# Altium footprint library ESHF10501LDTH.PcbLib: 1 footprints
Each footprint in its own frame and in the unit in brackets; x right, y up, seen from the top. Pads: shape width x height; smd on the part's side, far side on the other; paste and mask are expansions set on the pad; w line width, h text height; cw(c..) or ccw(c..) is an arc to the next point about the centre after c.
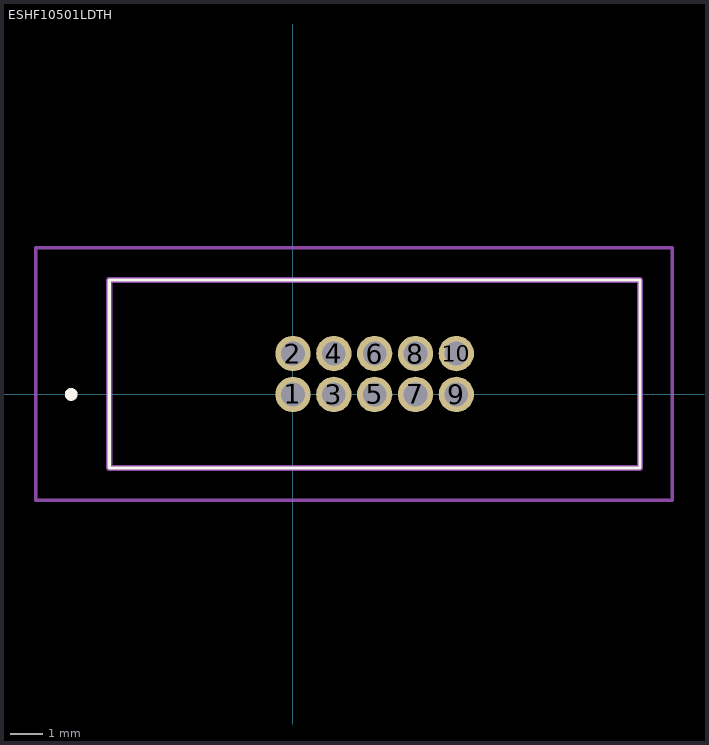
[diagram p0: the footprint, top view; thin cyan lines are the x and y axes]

## ESHF10501LDTH [mm]
pads (10):
  round 1.1 hole 0.74: 1(0,0) 2(0,1.27) 3(1.27,0) 4(1.27,1.27) 5(2.54,0) 6(2.54,1.27) 7(3.81,0) 8(3.81,1.27) 9(5.08,0) 10(5.08,1.27)
Top Overlay:
  lines w0.1: -5.715,-2.29 10.795,-2.29 10.795,3.56 -5.715,3.56 -5.715,-2.29
  lines w0.2: -7,0 -7,0 ; -7,0 ccw(c-6.9,0) -6.8,0 ; -7,0 cw(c-6.9,0) -6.8,0 ; -6.8,0 -6.8,0
Mechanical 15:
  lines w0.2: -5.715,-2.29 10.795,-2.29 10.795,3.56 -5.715,3.56 -5.715,-2.29
Mechanical 20:
  lines w0.1: -8,-3.29 11.795,-3.29 11.795,4.56 -8,4.56 -8,-3.29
